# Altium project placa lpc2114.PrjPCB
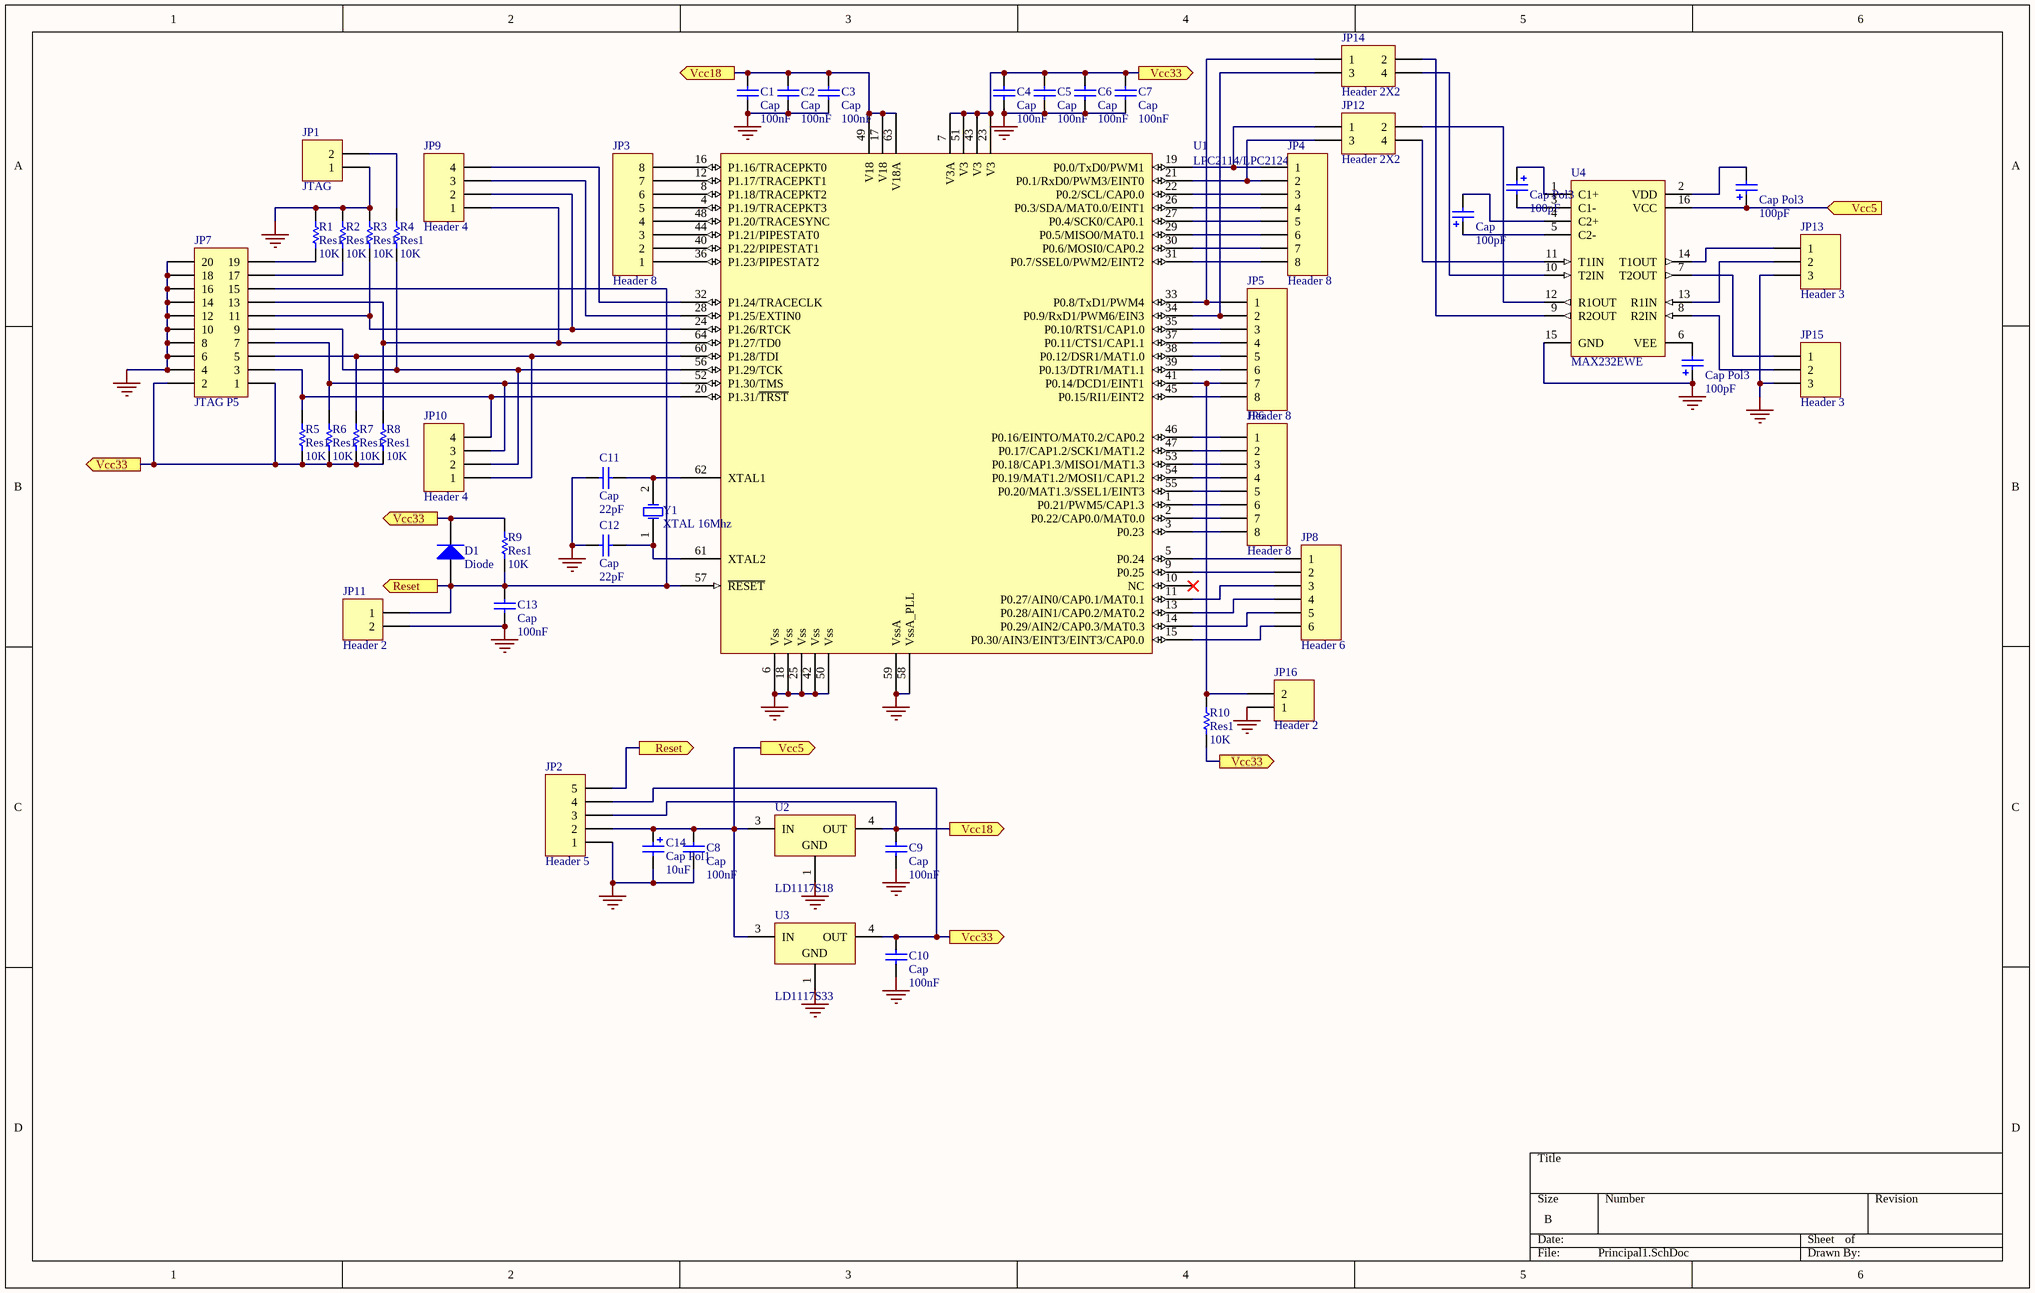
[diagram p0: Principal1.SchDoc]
1 sheet, 50 parts. Net scope: flat (ports and power ports of the same name join across sheets).
Board file: Principal.PcbDoc

## Sheet Principal1.SchDoc
size B

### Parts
C1  Cap  value 100nF  [R2012-0805]
C2  Cap  value 100nF  [R2012-0805]
C3  Cap  value 100nF  [R2012-0805]
C4  Cap  value 100nF  [R2012-0805]
C5  Cap  value 100nF  [R2012-0805]
C6  Cap  value 100nF  [R2012-0805]
C7  Cap  value 100nF  [R2012-0805]
C8  Cap  value 100nF  [R2012-0805]
C9  Cap  value 100nF  [R2012-0805]
C10  Cap  value 100nF  [R2012-0805]
C11  Cap  value 22pF  [Res 5mm]
C12  Cap  value 22pF  [Res 5mm]
C13  Cap  value 100nF  [Res 5mm]
C14  Cap Pol1  value 10uF  [RB5-10.5]
C15  Cap Pol3  value 100pF  [CC2012-0805]
C16  Cap Pol3  value 100pF  [CC2012-0805]
C17  Cap Pol3  value 100pF  [CC2012-0805]
C18  Cap  value 100pF  [CC2012-0805]
D1  Diode  [DIODE-0.4]
JP1  JTAG  [HDR1X2]
JP2  Header 5  [HDR1X5]
JP3  Header 8  [HDR1X8]
JP4  Header 8  [HDR1X8]
JP5  Header 8  [HDR1X8]
JP6  Header 8  [HDR1X8]
JP7  JTAG P5  [HDR2X10]
JP8  Header 6  [HDR1X6]
JP9  Header 4  [HDR1X4]
JP10  Header 4  [HDR1X4]
JP11  Header 2  [SW1]
JP12  Header 2X2  [HDR2X2]
JP13  Header 3  [HDR1X3]
JP14  Header 2X2  [HDR2X2]
JP15  Header 3  [HDR1X3]
JP16  Header 2  [SW1]
R1  Res1  value 10K  [Res 5mm]
R2  Res1  value 10K  [Res 5mm]
R3  Res1  value 10K  [Res 5mm]
R4  Res1  value 10K  [Res 5mm]
R5  Res1  value 10K  [Res 5mm]
R6  Res1  value 10K  [Res 5mm]
R7  Res1  value 10K  [Res 5mm]
R8  Res1  value 10K  [Res 5mm]
R9  Res1  value 10K  [Res 5mm]
R10  Res1  value 10K  [Res 5mm]
U1  LPC2114/LPC2124  [F-QFP10X10-G64/P.5N]
U2  LD1117S18  [SOT223]
U3  LD1117S33  [SOT223]
U4  MAX232EWE  [SO-G16]
Y1  XTAL 16Mhz  [BCY-W2/D3.1]

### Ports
Reset (out), Vcc5 (in), Vcc5 (out), Vcc18 (out), Vcc33 (out)

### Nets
GND: C1.1 C2.1 C3.1 C4.1 C5.1 C6.1 C7.1 C8.1 C9.1 C10.1 C11.2 C12.2 C13.2 C14.2 C17.1 JP1.1 JP2.1 JP7.4 JP7.6 JP7.8 JP7.10 JP7.12 JP7.14 JP7.16 JP7.18 JP7.20 JP11.2 JP13.3 JP15.3 JP16.1 R1.2 R2.2 R3.2 U1.6(Vss) U1.18(Vss) U1.25(Vss) U1.42(Vss) U1.50(Vss) U1.58(VssA_PLL) U1.59(VssA) U2.1(GND) U3.1(GND) U4.15(GND)
NetC1_2: C1.2 C2.2 C3.2 C9.2 JP2.3 U1.17(V18) U1.49(V18) U1.63(V18A) U2.4(OUT) ; port Vcc18
NetC4_2: C4.2 C5.2 C6.2 C7.2 C10.2 D1.2(K) JP2.4 JP7.1 JP7.2 R5.1 R6.1 R7.1 R8.1 R9.2 R10.1 U1.7(V3A) U1.23(V3) U1.43(V3) U1.51(V3) U3.4(OUT) ; port Vcc33
NetC8_2: C8.2 C14.1 C16.1 JP2.2 U2.3(IN) U3.3(IN) U4.16(VCC) ; port Vcc5
NetC11_1: C11.1 U1.62(XTAL1) Y1.2(OSC2)
NetC12_1: C12.1 U1.61(XTAL2) Y1.1(OSC1)
NetC13_1: C13.1 D1.1(A) JP2.5 JP7.15 JP11.1 R9.1 U1.57(~{RESET}) ; port Reset
NetC15_1: C15.1 U4.1(C1+)
NetC15_2: C15.2 U4.3(C1-)
NetC16_2: C16.2 U4.2(VDD)
NetC17_2: C17.2 U4.6(VEE)
NetC18_1: C18.1 U4.5(C2-)
NetC18_2: C18.2 U4.4(C2+)
NetJP1_2: JP1.2 R4.2
NetJP3_1: JP3.1 U1.36(P1.23/PIPESTAT2)
NetJP3_2: JP3.2 U1.40(P1.22/PIPESTAT1)
NetJP3_3: JP3.3 U1.44(P1.21/PIPESTAT0)
NetJP3_4: JP3.4 U1.48(P1.20/TRACESYNC)
NetJP3_5: JP3.5 U1.4(P1.19/TRACEPKT3)
NetJP3_6: JP3.6 U1.8(P1.18/TRACEPKT2)
NetJP3_7: JP3.7 U1.12(P1.17/TRACEPKT1)
NetJP3_8: JP3.8 U1.16(P1.16/TRACEPKT0)
NetJP4_1: JP4.1 JP12.1 U1.19(P0.0/TxD0/PWM1)
NetJP4_2: JP4.2 JP12.3 U1.21(P0.1/RxD0/PWM3/EINT0)
NetJP4_3: JP4.3 U1.22(P0.2/SCL/CAP0.0)
NetJP4_4: JP4.4 U1.26(P0.3/SDA/MAT0.0/EINT1)
NetJP4_5: JP4.5 U1.27(P0.4/SCK0/CAP0.1)
NetJP4_6: JP4.6 U1.29(P0.5/MISO0/MAT0.1)
NetJP4_7: JP4.7 U1.30(P0.6/MOSI0/CAP0.2)
NetJP4_8: JP4.8 U1.31(P0.7/SSEL0/PWM2/EINT2)
NetJP5_1: JP5.1 JP5.2 JP14.1 JP14.3 U1.33(P0.8/TxD1/PWM4) U1.34(P0.9/RxD1/PWM6/EIN3)
NetJP5_3: JP5.3 U1.35(P0.10/RTS1/CAP1.0)
NetJP5_4: JP5.4 U1.37(P0.11/CTS1/CAP1.1)
NetJP5_5: JP5.5 U1.38(P0.12/DSR1/MAT1.0)
NetJP5_6: JP5.6 U1.39(P0.13/DTR1/MAT1.1)
NetJP5_7: JP5.7 JP16.2 R10.2 U1.41(P0.14/DCD1/EINT1)
NetJP5_8: JP5.8 U1.45(P0.15/RI1/EINT2)
NetJP6_1: JP6.1 U1.46(P0.16/EINTO/MAT0.2/CAP0.2)
NetJP6_2: JP6.2 U1.47(P0.17/CAP1.2/SCK1/MAT1.2)
NetJP6_3: JP6.3 U1.53(P0.18/CAP1.3/MISO1/MAT1.3)
NetJP6_4: JP6.4 U1.54(P0.19/MAT1.2/MOSI1/CAP1.2)
NetJP6_5: JP6.5 U1.55(P0.20/MAT1.3/SSEL1/EINT3)
NetJP6_6: JP6.6 U1.1(P0.21/PWM5/CAP1.3)
NetJP6_7: JP6.7 U1.2(P0.22/CAP0.0/MAT0.0)
NetJP6_8: JP6.8 U1.3(P0.23)
NetJP7_3: JP7.3 JP10.4 R5.2 U1.20(P1.31/~{TRST})
NetJP7_5: JP7.5 JP10.1 R7.2 U1.60(P1.28/TDI)
NetJP7_7: JP7.7 JP10.3 R6.2 U1.52(P1.30/TMS)
NetJP7_9: JP7.9 JP10.2 R4.1 U1.56(P1.29/TCK)
NetJP7_11: JP7.11 JP9.2 R3.1 U1.24(P1.26/RTCK)
NetJP7_13: JP7.13 JP9.1 R8.2 U1.64(P1.27/TD0)
NetJP7_17: JP7.17 R2.1
NetJP7_19: JP7.19 R1.1
NetJP8_1: JP8.1 U1.5(P0.24)
NetJP8_2: JP8.2 U1.9(P0.25)
NetJP8_3: JP8.3 U1.11(P0.27/AIN0/CAP0.1/MAT0.1)
NetJP8_4: JP8.4 U1.13(P0.28/AIN1/CAP0.2/MAT0.2)
NetJP8_5: JP8.5 U1.14(P0.29/AIN2/CAP0.3/MAT0.3)
NetJP8_6: JP8.6 U1.15(P0.30/AIN3/EINT3/EINT3/CAP0.0)
NetJP9_3: JP9.3 U1.28(P1.25/EXTIN0)
NetJP9_4: JP9.4 U1.32(P1.24/TRACECLK)
NetJP12_2: JP12.2 U4.12(R1OUT)
NetJP12_4: JP12.4 U4.11(T1IN)
NetJP13_1: JP13.1 U4.14(T1OUT)
NetJP13_2: JP13.2 U4.13(R1IN)
NetJP14_2: JP14.2 U4.9(R2OUT)
NetJP14_4: JP14.4 U4.10(T2IN)
NetJP15_1: JP15.1 U4.7(T2OUT)
NetJP15_2: JP15.2 U4.8(R2IN)

Not connected (* = marked no-connect by the designer): U1 10(NC)*

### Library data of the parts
C1-C13 = Cap: Capacitor; Manufacturer: Generic Components; Class I: Passive
C14 = Cap Pol1: Polarized Capacitor (Radial); Manufacturer: Generic Components; Class I: Passive
C15-C18 = Cap Pol3: Polarized Capacitor (Surface Mount); Manufacturer: Generic Components; Class I: Passive
D1 = Diode: Default Diode; Manufacturer: Generic Components; Class I: Discrete; Class II: Diode - Switching
JP1 JP11 JP16 = Header 2: Header, 2-Pin; Manufacturer: Generic Components; Class I: Connector
JP2 = Header 5: Header, 5-Pin; Manufacturer: Generic Components; Class I: Connector
JP3-JP6 = Header 8: Header, 8-Pin; Manufacturer: Generic Components; Class I: Connector
JP7 = Header 10X2: Header, 10-Pin, Dual row; Manufacturer: Generic Components; Class I: Connector
JP8 = Header 6: Header, 6-Pin; Manufacturer: Generic Components; Class I: Connector
JP9 JP10 = Header 4: Header, 4-Pin; Manufacturer: Generic Components; Class I: Connector
JP12 JP14 = Header 2X2: Header, 2-Pin, Dual row; Manufacturer: Generic Components; Class I: Connector
JP13 JP15 = Header 3: Header, 3-Pin; Manufacturer: Generic Components; Class I: Connector
R1-R10 = Res1: Resistor; Manufacturer: Generic Components; Class I: Passive
U2 U3 = LF27ACDT: Very Low Drop Voltage Regulator with Inhibit; Manufacturer: ST-Microelectronics; Class I: Power Management
U4 = MAX232EWE: +5V Powered RS-232 Driver/Receiver; Manufacturer: Maxim; Class I: Communication; Class II: Transceiver
Y1 = XTAL: Crystal Oscillator; Manufacturer: Generic Components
